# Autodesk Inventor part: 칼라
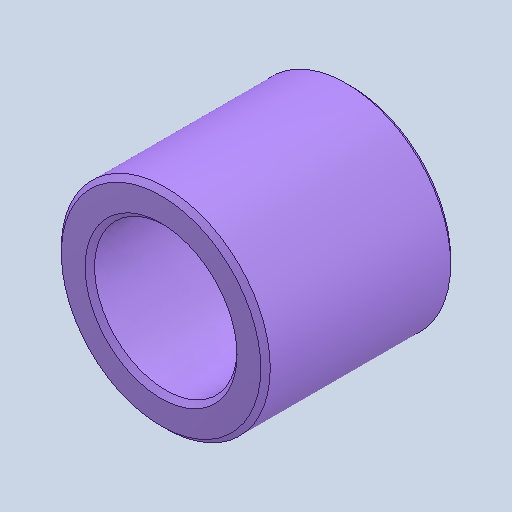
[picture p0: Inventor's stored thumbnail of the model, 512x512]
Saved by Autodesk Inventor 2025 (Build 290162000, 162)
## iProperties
Created: 2024-07
Part Number: 칼라
Material: 스테인리스강
Document SubType Name: Modeling
Designer: onair
Density: 8.08 g/cm^3
Appearance: 기본값
Author: jhkim
Sending System: Autodesk Inventor 2025
Preprocessor: ST-DEVELOPER v20
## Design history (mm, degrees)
feature "솔리드1"
node "솔리드2"
